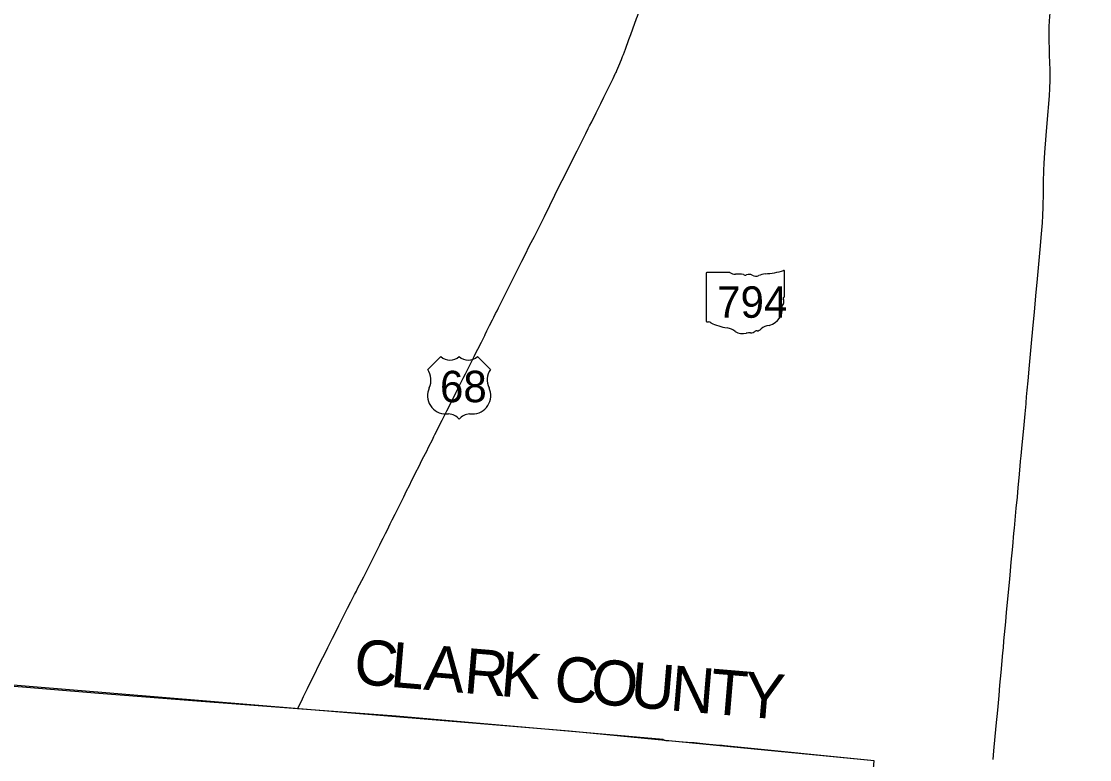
# Model space of a CAD drawing. Extents: x 0 to 34, y 0 to 22.
# Drawn here: x 6.6493 to 7.0296, y 15.5109 to 15.7738 of the extents above; entities that cross this region are included whole.
import ezdxf

# ---------------------------------------------------------------- set-up
doc = ezdxf.new("R2010")
doc.units = 0
for name, color, linetype in [('GM_X_County', 7, 'Continuous'), ('GM_X_County_Text', 7, 'Continuous'), ('GM_X_State_Location', 7, 'Continuous'), ('GM_X_State_Route', 7, 'Continuous'), ('GM_X_State_Shield', 7, 'Continuous'), ('GM_X_US_Location', 7, 'Continuous'), ('GM_X_US_Route', 7, 'Continuous'), ('GM_X_US_Shield', 7, 'Continuous'), ('SC_Scratch1', 7, 'Continuous')]:
    doc.layers.add(name, color=color, linetype=linetype)

msp = doc.modelspace()

# ---------------------------------------------------------------- linework, layer by layer
at = {"layer": 'GM_X_County'}
msp.add_lwpolyline([(6.952855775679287, 15.510459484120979), (6.899593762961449, 15.515744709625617), (6.8991608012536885, 15.51580693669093), (6.898757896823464, 15.51586705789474), (6.896653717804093, 15.516081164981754), (6.892968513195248, 15.516432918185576), (6.888754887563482, 15.516812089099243), (6.886384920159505, 15.517024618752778), (6.883484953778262, 15.51725191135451), (6.879793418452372, 15.517557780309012), (6.879143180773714, 15.517607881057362), (6.878870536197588, 15.517640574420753), (6.878479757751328, 15.51769647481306), (6.878222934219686, 15.517757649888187), (6.878087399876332, 15.517804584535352), (6.877968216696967, 15.517874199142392), (6.877855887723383, 15.517993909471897), (6.877783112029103, 15.518085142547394), (6.782695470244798, 15.52641430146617), (6.747555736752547, 15.528966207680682), (6.713326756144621, 15.531565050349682), (6.676821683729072, 15.534383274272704), (6.544854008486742, 15.54536559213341)], dxfattribs=at)
at = {"layer": 'GM_X_State_Route'}
for points in [[(7.01531030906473, 15.762286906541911), (7.015233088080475, 15.76446887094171), (7.015179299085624, 15.766312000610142), (7.0151782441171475, 15.769475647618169), (7.015213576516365, 15.771847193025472), (7.015297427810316, 15.773952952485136), (7.015489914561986, 15.776845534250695), (7.0157082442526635, 15.779207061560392), (7.016507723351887, 15.786813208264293), (7.016643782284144, 15.788117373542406)], [(7.010898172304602, 15.680807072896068), (7.011602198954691, 15.688625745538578), (7.012000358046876, 15.69256039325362), (7.012471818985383, 15.698078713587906), (7.012775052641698, 15.702023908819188), (7.01292007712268, 15.704658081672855), (7.013047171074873, 15.707557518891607), (7.013134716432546, 15.712831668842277), (7.013126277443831, 15.716523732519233), (7.013209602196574, 15.720739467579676), (7.0133192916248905, 15.723107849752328), (7.01359457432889, 15.727051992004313), (7.014100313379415, 15.733095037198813), (7.01445470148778, 15.737563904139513), (7.0152689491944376, 15.74728635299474), (7.015426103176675, 15.749920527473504), (7.01553685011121, 15.752819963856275), (7.015556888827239, 15.754141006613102), (7.01551100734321, 15.756515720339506), (7.015331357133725, 15.761686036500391)], [(7.015331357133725, 15.761686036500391), (7.0153195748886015, 15.762025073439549), (7.01531030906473, 15.762286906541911)], [(6.9952523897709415, 15.510877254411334), (6.995507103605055, 15.514031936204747), (6.996311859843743, 15.522959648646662), (6.996830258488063, 15.528472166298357), (6.997320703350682, 15.533723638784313), (6.99763554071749, 15.537401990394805), (6.99805637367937, 15.541864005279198), (6.9987203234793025, 15.54895227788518), (6.9988611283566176, 15.550676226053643), (6.99907049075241, 15.553156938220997), (6.999712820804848, 15.559981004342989), (7.000028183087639, 15.563393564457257), (7.001137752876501, 15.575206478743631), (7.001375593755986, 15.578075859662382), (7.001665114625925, 15.581245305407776), (7.002196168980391, 15.58675676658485), (7.00262596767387, 15.591483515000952), (7.002808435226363, 15.593319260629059), (7.0034671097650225, 15.60040859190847), (7.003832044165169, 15.60434640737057), (7.004133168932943, 15.60776213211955), (7.004454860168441, 15.611174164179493), (7.004846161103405, 15.615374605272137), (7.004991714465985, 15.61721457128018), (7.005155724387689, 15.619050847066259), (7.005539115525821, 15.622986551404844), (7.00609442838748, 15.62876169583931), (7.006583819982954, 15.634012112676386), (7.006929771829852, 15.637607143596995), (7.006962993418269, 15.637949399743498), (7.007143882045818, 15.640051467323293), (7.007351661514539, 15.642414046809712), (7.00766755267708, 15.64582660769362), (7.00817012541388, 15.651341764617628), (7.009031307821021, 15.660529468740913), (7.009586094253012, 15.666834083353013), (7.009928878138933, 15.6702440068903), (7.010183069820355, 15.673133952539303), (7.010571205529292, 15.67733439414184), (7.010898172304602, 15.680807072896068)]]:
    msp.add_lwpolyline(points, dxfattribs=at)
at = {"layer": 'GM_X_State_Shield'}
for p, q in [((6.893021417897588, 15.68402029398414), (6.893021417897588, 15.66703591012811)), ((6.9014885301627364, 15.684312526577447), (6.8932967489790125, 15.684312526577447)), ((6.920993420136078, 15.67584868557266), (6.920993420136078, 15.684733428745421)), ((6.920990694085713, 15.675850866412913), (6.920993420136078, 15.67584868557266))]:
    msp.add_line(p, q, dxfattribs=at)
for centre, major_axis, ratio, start_param, end_param in [((6.8933418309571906, 15.684056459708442), (0.00032405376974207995, 0), 0.7999999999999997, 1.7126933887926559, 3.283489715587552), ((6.903439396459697, 15.686284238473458), (0.0031431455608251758, 0), 0.8000000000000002, 4.042522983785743, 4.731795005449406), ((6.904481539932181, 15.67477730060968), (0.011283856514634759, 0), 0.7999999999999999, 1.4047577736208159, 1.6578580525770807), ((6.907043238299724, 15.684144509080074), (0.0009067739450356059, 0), 0.8, 3.836095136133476, 5.185414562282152), ((6.908374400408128, 15.682181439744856), (0.001885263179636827, 0), 0.8000000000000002, 0.9506229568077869, 2.0794050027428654), ((6.910807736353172, 15.684873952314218), (0.0022679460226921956, 0), 0.8, 4.0815607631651, 5.145722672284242), ((6.914813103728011, 15.679124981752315), (0.005967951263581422, 0), 0.8000000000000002, 1.6990113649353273, 2.107814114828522), ((6.911029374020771, 15.70746803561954), (0.029664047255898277, 0), 0.7999999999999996, 4.81439421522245, 5.042368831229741), ((6.9206831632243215, 15.684770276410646), (0.00031139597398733, 0), 0.8000000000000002, 6.141151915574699, 7.989035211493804), ((6.920921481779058, 15.675196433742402), (0.0004819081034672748, 0), 0.8000000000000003, 1.8839779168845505, 3.671072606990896), ((6.920661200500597, 15.675814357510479), (0.0003332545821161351, 0), 0.8, 5.054540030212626, 6.418171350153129), ((6.912691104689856, 15.671000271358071), (0.007419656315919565, 0), 0.8000000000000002, 5.1017524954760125, 6.440017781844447), ((6.9221091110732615, 15.672130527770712), (0.0021047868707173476, 0), 0.7999999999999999, 2.3877238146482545, 3.2625368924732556), ((6.91785562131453, 15.674073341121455), (0.00289289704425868, 0), 0.8, 5.934694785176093, 6.69594811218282), ((6.893344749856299, 15.66699873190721), (0.00032693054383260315, 0), 0.7999999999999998, 3.0012400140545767, 4.508300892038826), ((6.893394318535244, 15.66873637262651), (0.0024948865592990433, 0), 0.8, 4.6659456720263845, 4.897461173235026), ((6.893904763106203, 15.666056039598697), (0.0008996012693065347, 0), 0.8000000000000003, 0.5192071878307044, 1.6278990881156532), ((6.905262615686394, 15.68131580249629), (0.02142156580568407, 0), 0.7999999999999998, 4.195997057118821, 4.488960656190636), ((6.898876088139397, 15.659405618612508), (0.006702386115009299, 0), 0.8, 0.8235188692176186, 1.3235874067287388), ((6.910671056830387, 15.665389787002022), (0.002397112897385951, 0), 0.8000000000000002, 4.93706856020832, 5.642249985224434), ((6.915819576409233, 15.662267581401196), (0.004063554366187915, 0), 0.8000000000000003, 1.6476453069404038, 2.4884337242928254), ((6.9061251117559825, 15.665971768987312), (0.004253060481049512, 0), 0.8000000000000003, 4.0264810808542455, 4.996735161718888), ((6.908582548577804, 15.660099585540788), (0.003494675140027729, 0), 0.7999999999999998, 1.4956620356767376, 1.9409797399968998), ((6.908893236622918, 15.664699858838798), (0.002266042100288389, 0), 0.8, 4.691043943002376, 5.507373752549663), ((6.910943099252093, 15.663054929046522), (0.000637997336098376, 0), 0.8000000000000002, 1.1475841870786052, 2.315151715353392)]:
    msp.add_ellipse(centre, major_axis=major_axis, ratio=ratio, start_param=start_param, end_param=end_param, dxfattribs=at)
at = {"layer": 'GM_X_US_Route'}
for points in [[(6.863303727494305, 15.761295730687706), (6.863584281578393, 15.762021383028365), (6.864296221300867, 15.763933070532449), (6.865523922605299, 15.767267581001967), (6.866193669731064, 15.769109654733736), (6.86691826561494, 15.771065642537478), (6.868275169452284, 15.774783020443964), (6.868585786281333, 15.775617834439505), (6.869195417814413, 15.777254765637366), (6.870792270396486, 15.781444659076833), (6.871670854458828, 15.783649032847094), (6.872467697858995, 15.785682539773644), (6.873011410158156, 15.787069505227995), (6.8750718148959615, 15.792233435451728), (6.877920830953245, 15.799396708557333)], [(6.851074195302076, 15.735577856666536), (6.851570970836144, 15.736570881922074), (6.852296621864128, 15.738046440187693), (6.8539008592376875, 15.741244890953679), (6.855533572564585, 15.744496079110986), (6.856656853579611, 15.74678694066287), (6.858760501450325, 15.751043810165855), (6.85979887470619, 15.753135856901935), (6.859970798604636, 15.753481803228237), (6.860710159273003, 15.755044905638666), (6.860929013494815, 15.755516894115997), (6.860975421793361, 15.755616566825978), (6.861268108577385, 15.75625889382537), (6.861617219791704, 15.757110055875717), (6.861985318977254, 15.757984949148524), (6.862874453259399, 15.760187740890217), (6.863303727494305, 15.761295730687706)], [(6.810512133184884, 15.65455076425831), (6.813046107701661, 15.659591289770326), (6.814214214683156, 15.661951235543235), (6.814384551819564, 15.662296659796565), (6.815027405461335, 15.663595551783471), (6.815976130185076, 15.665479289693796), (6.816994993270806, 15.66750278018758), (6.817469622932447, 15.668458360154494), (6.8181114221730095, 15.669749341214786), (6.818613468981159, 15.67072601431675), (6.81912975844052, 15.671758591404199), (6.81986753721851, 15.673198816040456), (6.820706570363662, 15.674883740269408), (6.8218646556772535, 15.677214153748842), (6.8230506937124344, 15.679586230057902), (6.824362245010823, 15.682223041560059), (6.825673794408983, 15.684818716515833), (6.8274177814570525, 15.688348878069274), (6.828575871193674, 15.69065081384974), (6.8302222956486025, 15.693943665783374), (6.83189667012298, 15.697222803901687), (6.833459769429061, 15.700292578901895), (6.835469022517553, 15.704283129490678), (6.837408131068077, 15.70823201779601), (6.839187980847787, 15.711851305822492), (6.840548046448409, 15.714594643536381), (6.841831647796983, 15.717064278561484), (6.847092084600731, 15.727626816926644), (6.848808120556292, 15.731017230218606), (6.8502035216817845, 15.733835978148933), (6.851074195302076, 15.735577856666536)], [(6.7894682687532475, 15.612650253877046), (6.790232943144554, 15.61417380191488), (6.790367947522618, 15.614441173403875), (6.7914047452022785, 15.616489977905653), (6.792130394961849, 15.617941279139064), (6.793609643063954, 15.620773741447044), (6.7942514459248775, 15.622099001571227), (6.795702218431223, 15.624973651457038), (6.795901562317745, 15.625393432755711), (6.796143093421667, 15.625901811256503), (6.796483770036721, 15.626620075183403), (6.79912110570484, 15.631796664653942), (6.800153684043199, 15.63390347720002), (6.800767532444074, 15.635131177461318), (6.802581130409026, 15.638731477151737), (6.804088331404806, 15.6417311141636), (6.805274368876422, 15.644089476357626), (6.806573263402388, 15.646669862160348), (6.807395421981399, 15.648303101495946), (6.808679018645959, 15.650912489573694), (6.810464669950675, 15.654456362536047), (6.810512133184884, 15.65455076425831)], [(6.76154250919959, 15.55706818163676), (6.762312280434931, 15.558598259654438), (6.7629403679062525, 15.559881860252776), (6.765410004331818, 15.564779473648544), (6.766568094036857, 15.56708193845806), (6.767907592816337, 15.569705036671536), (6.768532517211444, 15.570909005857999), (6.768982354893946, 15.571783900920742), (6.771145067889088, 15.576011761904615), (6.7737539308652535, 15.581174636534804), (6.775191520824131, 15.584007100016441), (6.776837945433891, 15.587327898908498), (6.777535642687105, 15.588723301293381), (6.778037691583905, 15.589699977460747), (6.778916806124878, 15.591443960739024), (6.779558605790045, 15.592727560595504), (6.780604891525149, 15.59482066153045), (6.7813168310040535, 15.59622977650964), (6.782363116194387, 15.598350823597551), (6.783758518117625, 15.601169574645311), (6.785404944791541, 15.604490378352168), (6.786437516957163, 15.60655552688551), (6.787400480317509, 15.608494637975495), (6.788334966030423, 15.61039261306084), (6.7894682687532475, 15.612650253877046)], [(6.758099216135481, 15.550202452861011), (6.758405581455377, 15.550798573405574), (6.760079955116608, 15.554161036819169), (6.76154250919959, 15.55706818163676)], [(6.753534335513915, 15.541111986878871), (6.753940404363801, 15.541924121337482), (6.754847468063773, 15.543807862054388), (6.756605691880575, 15.547296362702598), (6.758099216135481, 15.550202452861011)], [(6.74932760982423, 15.532522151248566), (6.749740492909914, 15.533370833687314), (6.7511358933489, 15.53621753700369), (6.75234935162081, 15.538708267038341), (6.752980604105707, 15.540004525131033), (6.753534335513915, 15.541111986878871)], [(6.7475751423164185, 15.528920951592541), (6.7482390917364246, 15.530284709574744), (6.74932760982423, 15.532522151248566)]]:
    msp.add_lwpolyline(points, dxfattribs=at)
at = {"layer": 'GM_X_US_Shield'}
for p, q in [((6.798587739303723, 15.654480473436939), (6.79392563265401, 15.649818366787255)), ((6.816303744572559, 15.649818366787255), (6.811641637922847, 15.654480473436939)), ((6.8004525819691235, 15.633967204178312), (6.8013850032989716, 15.633967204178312)), ((6.808844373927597, 15.633967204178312), (6.80977679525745, 15.633967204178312))]:
    msp.add_line(p, q, dxfattribs=at)
for centre, radius, start, end in [((6.801851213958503, 15.657809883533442), 0.004662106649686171, 225.57299599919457, 314.4270040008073), ((6.808378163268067, 15.657809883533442), 0.004662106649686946, 225.57299599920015, 314.4270040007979), ((6.788579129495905, 15.646074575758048), 0.006526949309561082, 334.5471236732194, 35.000929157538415), ((6.821650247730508, 15.646074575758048), 0.006526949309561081, 144.99907084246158, 205.4528763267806), ((6.8003798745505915, 15.640493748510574), 0.006526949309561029, 154.8319194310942, 270.63826363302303), ((6.809849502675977, 15.640493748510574), 0.006526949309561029, 269.36173636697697, 25.168080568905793), ((6.801385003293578, 15.629305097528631), 0.0046621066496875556, 36.86989764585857, 89.99999993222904), ((6.808844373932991, 15.629305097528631), 0.0046621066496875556, 90.00000006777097, 143.13010235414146)]:
    msp.add_arc(centre, radius, start, end, dxfattribs=at)
at = {"layer": 'SC_Scratch1'}
msp.add_lwpolyline([(7.728068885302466, 15.222842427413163), (7.483318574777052, 15.249243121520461), (7.347774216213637, 15.261864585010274), (7.340251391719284, 15.30712070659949), (7.224896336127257, 15.322951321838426), (6.985824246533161, 15.357831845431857), (6.940184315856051, 15.364253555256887), (6.952855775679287, 15.510459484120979), (6.8442681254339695, 15.52102087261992), (6.474073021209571, 15.551659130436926), (6.438862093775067, 15.554685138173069), (6.447024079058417, 15.641986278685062), (6.28414536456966, 15.656640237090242), (6.133164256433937, 15.670879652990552)], dxfattribs=at)

# ---------------------------------------------------------------- texts
at = {"layer": 'GM_X_County_Text'}
for s, height, rotation, p in [('C', 0.016074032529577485, 355.195053, (6.7672280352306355, 15.537942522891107)), ('L', 0.016074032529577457, 355.195252, (6.780266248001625, 15.536846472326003)), ('A', 0.016074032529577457, 355.19545200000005, (6.79224739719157, 15.535839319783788)), ('R', 0.016074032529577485, 355.195053, (6.806413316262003, 15.534648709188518)), ('K', 0.016074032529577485, 355.195181, (6.819451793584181, 15.533552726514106)), ('C', 0.016074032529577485, 355.195053, (6.838480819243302, 15.531953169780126)), ('O', 0.016074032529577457, 355.19545200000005, (6.851519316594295, 15.530857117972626)), ('U', 0.016074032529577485, 355.195181, (6.8656852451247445, 15.529666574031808)), ('N', 0.016074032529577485, 355.195181, (6.879851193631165, 15.528475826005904)), ('T', 0.016074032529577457, 355.195252, (6.894017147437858, 15.527285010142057)), ('Y', 0.016074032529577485, 355.195181, (6.90599827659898, 15.526277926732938))]:
    msp.add_text(s, height=height, rotation=rotation, dxfattribs=at).set_placement(p)
at = {"layer": 'GM_X_State_Location'}
msp.add_text('794', height=1.6074032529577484e-05, rotation=1.0000000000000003e-05, dxfattribs=at).set_placement((6.901018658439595, 15.673229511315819))
for s, p in [('s', (6.906693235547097, 15.674398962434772)), ('r', (6.906692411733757, 15.674398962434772))]:
    msp.add_text(s, height=1.6074032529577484e-05, dxfattribs=at).set_placement(p)
at = {"layer": 'GM_X_State_Shield'}
msp.add_text('794', height=0.011189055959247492, dxfattribs=at).set_placement((6.8969697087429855, 15.668233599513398))
at = {"layer": 'GM_X_US_Location'}
for s, p in [('0', (6.805108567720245, 15.643669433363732)), ('/', (6.805110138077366, 15.643669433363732))]:
    msp.add_text(s, height=1.6074032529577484e-05, dxfattribs=at).set_placement(p)
msp.add_text('68', height=1.6074032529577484e-05, rotation=1.0000000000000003e-05, dxfattribs=at).set_placement((6.80179064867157, 15.640342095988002))
at = {"layer": 'GM_X_US_Shield'}
msp.add_text('68', height=0.011189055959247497, dxfattribs=at).set_placement((6.7983073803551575, 15.63816310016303))

doc.saveas('drawing.dxf')
